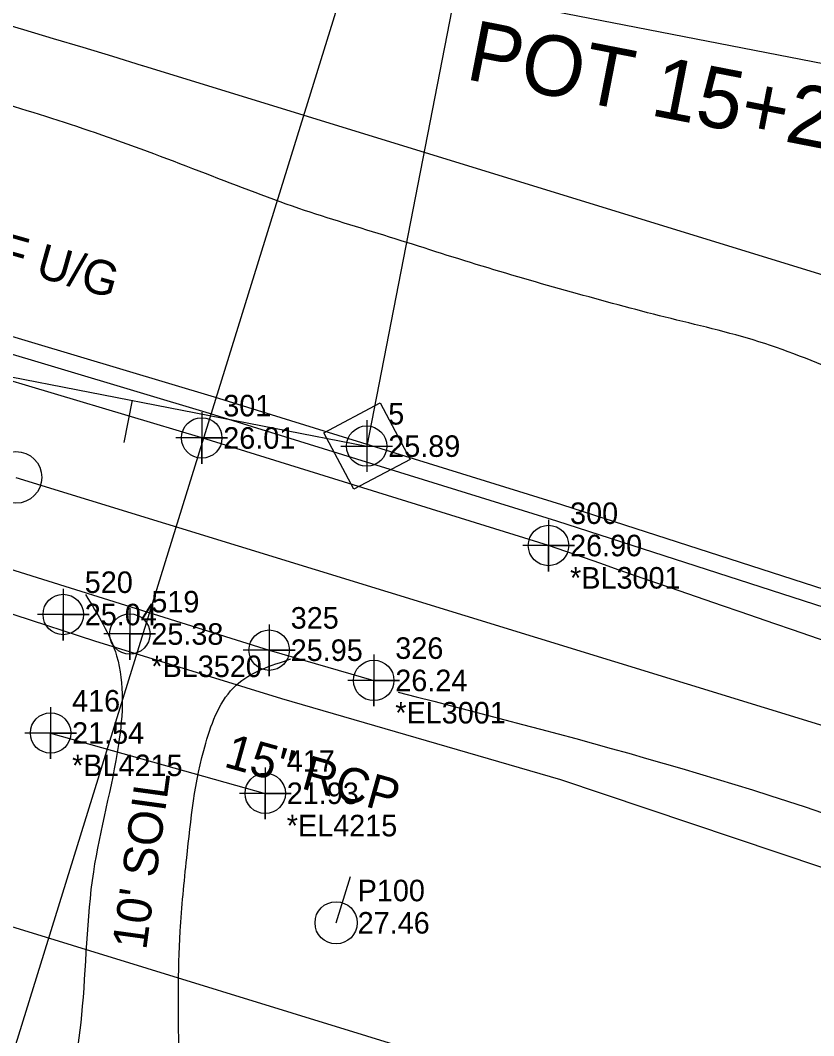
# Model space of a CAD drawing. Extents: x 2627243 to 2636458, y 566398 to 571062.
# Drawn here: x 2635089.6 to 2635181.7, y 568953.4 to 569071.3 of the extents above; entities that cross this region are included whole.
import ezdxf

# ---------------------------------------------------------------- set-up
doc = ezdxf.new("R2010")
doc.units = 0
for name, color, linetype in [('COGO Default Chain', 7, 'Continuous'), ('Cogo Default Point CELL', 7, 'Continuous'), ('COGO Default Point Elevation', 7, 'Continuous'), ('COGO Default Point Number', 7, 'Continuous'), ('CTL Supplemental Horizontal and Vertical CELL', 7, 'Continuous'), ('Default', 7, 'Continuous'), ('Exist Horizontal Alignment', 7, 'Continuous'), ('Exist Horizontal Alignment Point', 7, 'Continuous'), ('Exist Horizontal Baseline Alignment', 7, 'Continuous'), ('Exist Horizontal Baseline Alignment Station Label', 7, 'Continuous'), ('Exist Horizontal Baseline Alignment Tick small', 7, 'Continuous'), ('Exist Right of Way Line', 7, 'Continuous'), ('Exist Roads EOP', 7, 'Continuous'), ('Exist Roads EOP Cogo Comment', 7, 'Continuous'), ('Exist Roads EOP Cogo Elevation', 7, 'Continuous'), ('Exist Roads EOP Cogo Number', 7, 'Continuous'), ('Exist Roads EOP Cogo Point CELL', 7, 'Continuous'), ('Exist Roads Soil', 7, 'Continuous'), ('Exist Roads Soil Text', 7, 'Continuous'), ('Exist Structure Minor Pipes RCP 15 Inch', 7, 'Continuous'), ('Exist Structure Minor Pipes RCP 15 Inch Cogo Comment', 7, 'Continuous'), ('Exist Structure Minor Pipes RCP 15 Inch Cogo Elevation', 7, 'Continuous'), ('Exist Structure Minor Pipes RCP 15 Inch Cogo Number', 7, 'Continuous'), ('Exist Structure Minor Pipes RCP 15 Inch Cogo Point CELL', 7, 'Continuous'), ('Exist Structure Minor Pipes RCP 15 Inch Text', 7, 'Continuous'), ('Exist Utilities Power Pole CELL', 7, 'Continuous'), ('Exist Utilities Power Pole Cogo Elevation', 7, 'Continuous'), ('Exist Utilities Power Pole Cogo Number', 7, 'Continuous'), ('Exist Utilities Telephone UG Cable', 7, 'Continuous'), ('Exist Utilities Telephone UG Cable Text', 7, 'Continuous'), ('Exist Utilities Water UG Line Cogo Comment', 7, 'Continuous'), ('Exist Utilities Water UG Line Cogo Elevation', 7, 'Continuous'), ('Exist Utilities Water UG Line Cogo Number', 7, 'Continuous'), ('Exist Utilities Water UG Line Cogo Point CELL', 7, 'Continuous'), ('Exist Utilities Water UG Line SUE', 7, 'Continuous'), ('Exist Vegetation Woods Line', 7, 'Continuous'), ('Scratch_Level_2', 7, 'Continuous')]:
    doc.layers.add(name, color=color, linetype=linetype)

# ---------------------------------------------------------------- blocks, each defined once
blk = doc.blocks.new('COGO DEFAULT POINT')
at = {"layer": 'Cogo Default Point CELL'}
for points in [[(0, 0.06), (0, 0)], [(-0.06, 0), (0, 0)], [(0, 0), (0.06, 0)], [(0, 0), (0, -0.06)]]:
    blk.add_lwpolyline(points, dxfattribs=at)
blk.add_circle((0, 0), 0.0469, dxfattribs=at)
blk = doc.blocks.new('EXIST ROADS EOP COGO POINT')
at = {"layer": 'Exist Roads EOP Cogo Point CELL'}
blk.add_lwpolyline([(0, 0.06), (0, -0.06), (0, 0), (0.06, 0), (-0.06, 0)], dxfattribs=at)
blk.add_circle((0, 0), 0.0469, dxfattribs=at)
blk = doc.blocks.new('EXIST STRUCTURE MINOR PIPES RCP COGO POINT')
at = {"layer": 'Exist Structure Minor Pipes RCP 15 Inch Cogo Point CELL'}
blk.add_lwpolyline([(0, 0.06), (0, -0.06), (0, 0), (0.06, 0), (-0.06, 0)], dxfattribs=at)
blk.add_circle((0, 0), 0.0469, dxfattribs=at)
blk = doc.blocks.new('EXIST UTILITIES WATER UG LINE COGO POINT')
at = {"layer": 'Exist Utilities Water UG Line Cogo Point CELL'}
blk.add_lwpolyline([(0, 0.06), (0, -0.06), (0, 0), (0.06, 0), (-0.06, 0)], dxfattribs=at)
blk.add_circle((0, 0), 0.0469, dxfattribs=at)
blk = doc.blocks.new('EXIST UTILITIES POWER POLE')
at = {"layer": 'Exist Utilities Power Pole CELL'}
for q in [(0, 0.1125), (0, 0)]:
    blk.add_line((0, 0), q, dxfattribs=at)
blk.add_circle((0, 0), 0.049, dxfattribs=at)
blk = doc.blocks.new('CTL SUPPLEMENTAL HORIZONTAL AND VERTICAL')
at = {"layer": 'CTL Supplemental Horizontal and Vertical CELL'}
blk.add_line((0, 0), (0, 0), dxfattribs=at)
blk.add_lwpolyline([(-0.1043, 0.0004), (0.0005, 0.1052), (0.1055, 0.0002), (0.0007, -0.1047)], close=True, dxfattribs=at)

msp = doc.modelspace()

# ---------------------------------------------------------------- linework, layer by layer
at = {"layer": 'COGO Default Chain'}
msp.add_line((2635089.07, 569018.2), (2635391.77, 568925.15), dxfattribs=at)
msp.add_line((2635089.07, 569018.2), (2635391.77, 568925.15), dxfattribs=at)
at = {"layer": 'Exist Horizontal Alignment'}
msp.add_line((2635089.07, 569018.2), (2635391.77, 568925.15), dxfattribs=at)
at = {"layer": 'Exist Horizontal Alignment Point'}
msp.add_circle((2635089.07, 569018.2), 3, dxfattribs=at)
at = {"layer": 'Exist Horizontal Baseline Alignment'}
msp.add_line((2634680.61, 569109.43), (2635129.79, 569021.83), dxfattribs=at)
at = {"layer": 'Exist Horizontal Baseline Alignment Station Label'}
for q in [(2635129.79, 569021.83), (2635187.68, 569065.28)]:
    msp.add_line((2635140.07, 569074.57), q, dxfattribs=at)
at = {"layer": 'Exist Horizontal Baseline Alignment Tick small'}
msp.add_line((2635102.55, 569027.15), (2635101.59, 569022.24), dxfattribs=at)
at = {"layer": 'Exist Right of Way Line'}
for p, q in [((2635103.76, 569066), (2635803.01, 568851.04)), ((2635074.38, 568970.41), (2635740.72, 568765.57))]:
    msp.add_line(p, q, dxfattribs=at)
msp.add_arc((2634692.38, 567727.8), 1400, 72.91185, 82.32218, dxfattribs=at)
at = {"layer": 'Exist Roads EOP'}
for points in [[(2635150.9, 569010.29), (2635110.64, 569022.78), (2635067.86, 569035.57), (2635023.64, 569048.11), (2634984.83, 569056.94), (2634943.78, 569065.62), (2634903.89, 569072.16), (2634856.98, 569078.75), (2634806.21, 569085.47), (2634756.15, 569092.13), (2634708.47, 569098.26)], [(2634739.19, 569072.43), (2634781.28, 569066.95), (2634828.08, 569061.02), (2634863.8, 569056.89), (2634909.63, 569049.84), (2634954.36, 569041.99), (2634993.78, 569033.88), (2635035.22, 569023.11), (2635076.05, 569011.42), (2635118.47, 568998.14), (2635130.61, 568994.63)]]:
    msp.add_lwpolyline(points, dxfattribs=at)
for points in [[(2635667.16, 568849.05), (2635611.87, 568866.17), (2635537.66, 568888.99), (2635465.1, 568910.99), (2635418.27, 568925.45), (2635347.57, 568947.27), (2635276.81, 568969.36), (2635215.72, 568988.32), (2635150.9, 569010.29)], [(2635133.46, 568993.27), (2635198.85, 568973.26), (2635239.36, 568960.01), (2635248.88, 568959.46), (2635293.13, 568945.35), (2635367.48, 568922.3), (2635452.26, 568896.08), (2635526.55, 568873.61), (2635591.22, 568853.69), (2635664.39, 568831.49)]]:
    msp.add_spline(points, degree=3, dxfattribs=at)
at = {"layer": 'Exist Roads Soil'}
for points in [[(2635097.14, 569004.59), (2635100.76, 568997.47), (2635100.98, 568987.21), (2635098.06, 568972.41), (2635096.68, 568955.79), (2635094.68, 568941.66), (2635094.11, 568930.19), (2635096.85, 568919.53), (2635099.85, 568908.12), (2635102.17, 568895.97), (2635108.88, 568878.63), (2635115.77, 568864.28)], [(2635133.55, 568866.82), (2635129.28, 568877.14), (2635121.85, 568893), (2635113.93, 568911.65), (2635108.58, 568929.12), (2635107.96, 568937.38), (2635107.97, 568951.4), (2635108.13, 568965.51), (2635108.9, 568974.02), (2635111.1, 568987.34), (2635114.62, 568994.07), (2635121, 568997.12)]]:
    msp.add_spline(points, degree=3, dxfattribs=at)
at = {"layer": 'Exist Structure Minor Pipes RCP 15 Inch'}
msp.add_line((2635093.09, 568988.52), (2635118.01, 568981.52), dxfattribs=at)
at = {"layer": 'Exist Utilities Telephone UG Cable'}
for points in [[(2634914.07, 569075.55), (2634944.7, 569070.54), (2634985.9, 569061.82), (2635024.88, 569052.96), (2635069.26, 569040.37), (2635112.09, 569027.56), (2635152.41, 569015.06), (2635241.49, 568986.31)], [(2634912.04, 569073.86), (2634944.33, 569068.57), (2634985.47, 569059.87), (2635024.38, 569051.02), (2635068.7, 569038.45), (2635111.51, 569025.65), (2635151.81, 569013.15), (2635242.78, 568983.79)]]:
    msp.add_lwpolyline(points, dxfattribs=at)
at = {"layer": 'Exist Utilities Water UG Line SUE'}
msp.add_lwpolyline([(2634745.29, 569060.81), (2634772.3, 569060.34), (2634799.29, 569058.16), (2634834.92, 569055.15), (2634876.42, 569050.41), (2634893.17, 569047.22), (2634922.73, 569041.34), (2634951.3, 569036.03), (2634995.75, 569027.26), (2635043.17, 569015.78), (2635070.42, 569008.3), (2635098.21, 568999.23), (2635119.9, 568992.52), (2635152.3, 568983.11), (2635187.64, 568971.23), (2635214.87, 568960.8)], dxfattribs=at)
at = {"layer": 'Exist Vegetation Woods Line'}
msp.add_spline([(2635649.22, 568878.38), (2635649.32, 568878.23), (2635637.74, 568881.93), (2635627.68, 568886.16), (2635617.49, 568889.28), (2635607.89, 568892.77), (2635596.11, 568897.78), (2635585.94, 568901.53), (2635574.03, 568905.43), (2635563.97, 568908.01), (2635552.13, 568911.13), (2635540.53, 568914.2), (2635528.58, 568918.49), (2635517.15, 568923.92), (2635505.87, 568929.45), (2635493.79, 568934.28), (2635482.45, 568937.92), (2635472.8, 568941.17), (2635463.24, 568944.27), (2635450.66, 568948.58), (2635439.69, 568951.62), (2635428.91, 568954.37), (2635419.18, 568956.75), (2635408.99, 568959.87), (2635397.38, 568963.96), (2635387.75, 568967.84), (2635376.76, 568971.9), (2635365.81, 568975.58), (2635356.14, 568978.2), (2635343.89, 568980.65), (2635330.64, 568983.72), (2635319.31, 568987.36), (2635308.9, 568991.16), (2635296.37, 568995.71), (2635286.29, 568999.31), (2635275.75, 569003.66), (2635265.84, 569006.33), (2635254.74, 569009.92), (2635243.26, 569013.46), (2635232.29, 569016.51), (2635221.8, 569019.45), (2635210.06, 569022.42), (2635198.81, 569025.91), (2635186.75, 569029.72), (2635176, 569033.73), (2635165.13, 569036.63), (2635154.25, 569039.52), (2635143.19, 569042.72), (2635132.43, 569046.1), (2635121.91, 569049.42), (2635110.35, 569053.75), (2635098.3, 569058.19), (2635086.72, 569061.88), (2635075.7, 569064.69), (2635065.45, 569065.92), (2635055.37, 569067.87), (2635043.05, 569071.1), (2635032.79, 569073.35), (2635022.28, 569075.66), (2635011.74, 569078.35), (2635001.01, 569081.34), (2634990.29, 569084.33), (2634977.78, 569087.86), (2634972.57, 569088.94), (2634968.39, 569090.04), (2634959.01, 569094.49), (2634948.1, 569099.43), (2634938.51, 569104.57), (2634928.51, 569110.69), (2634919.34, 569115.47), (2634907.33, 569119.52), (2634897.4, 569121.57), (2634887.58, 569122.45)], degree=3, dxfattribs=at)
at = {"layer": 'Scratch_Level_2'}
for p, q in [((2635137.19, 569107.8), (2635107.6, 569012.28)), ((2635107.6, 569012.28), (2635078, 568916.76))]:
    msp.add_line(p, q, dxfattribs=at)

# ---------------------------------------------------------------- block references
at = {"layer": 'Cogo Default Point CELL', "xscale": 50, "yscale": 50}
msp.add_blockref('COGO DEFAULT POINT', (2635129.79, 569021.83), dxfattribs=at)
at = {"layer": 'CTL Supplemental Horizontal and Vertical CELL', "xscale": 50, "yscale": 49.99999999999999, "rotation": -17.088147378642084}
msp.add_blockref('CTL SUPPLEMENTAL HORIZONTAL AND VERTICAL', (2635129.79, 569021.83), dxfattribs=at)
at = {"layer": 'Exist Roads EOP Cogo Point CELL', "xscale": 50, "yscale": 50}
for p in [(2635110.64, 569022.78), (2635150.9, 569010.29), (2635118.47, 568998.14), (2635130.61, 568994.63)]:
    msp.add_blockref('EXIST ROADS EOP COGO POINT', p, dxfattribs=at)
at = {"layer": 'Exist Structure Minor Pipes RCP 15 Inch Cogo Point CELL', "xscale": 50, "yscale": 50}
for p in [(2635093.09, 568988.52), (2635118.01, 568981.52)]:
    msp.add_blockref('EXIST STRUCTURE MINOR PIPES RCP COGO POINT', p, dxfattribs=at)
at = {"layer": 'Exist Utilities Power Pole CELL', "xscale": 50, "yscale": 50.00000000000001, "rotation": -17.08814737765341}
msp.add_blockref('EXIST UTILITIES POWER POLE', (2635126.24, 568966.49), dxfattribs=at)
at = {"layer": 'Exist Utilities Water UG Line Cogo Point CELL', "xscale": 50, "yscale": 50}
for p in [(2635094.56, 569002.28), (2635102.29, 569000.02)]:
    msp.add_blockref('EXIST UTILITIES WATER UG LINE COGO POINT', p, dxfattribs=at)

# ---------------------------------------------------------------- texts
at = {"layer": 'COGO Default Point Elevation'}
msp.add_text('25.89', height=2.5, dxfattribs=at).set_placement((2635132.29, 569020.58))
at = {"layer": 'COGO Default Point Number'}
msp.add_text('5', height=2.5, dxfattribs=at).set_placement((2635132.29, 569024.33))
at = {"layer": 'Default'}
msp.add_text('POT 15+27.75 ', height=7, rotation=348.9655, dxfattribs=at).set_placement((2635141.13, 569064.46))
at = {"layer": 'Exist Roads EOP Cogo Comment'}
for s, p in [('*BL3001', (2635153.4, 569005.29)), ('*EL3001', (2635133.11, 568989.63))]:
    msp.add_text(s, height=2.5, dxfattribs=at).set_placement(p)
at = {"layer": 'Exist Roads EOP Cogo Elevation'}
for s, p in [('26.01', (2635113.14, 569021.53)), ('26.90', (2635153.4, 569009.04)), ('25.95', (2635120.97, 568996.89)), ('26.24', (2635133.11, 568993.38))]:
    msp.add_text(s, height=2.5, dxfattribs=at).set_placement(p)
at = {"layer": 'Exist Roads EOP Cogo Number'}
for s, p in [('301', (2635113.14, 569025.28)), ('300', (2635153.4, 569012.79)), ('325', (2635120.97, 569000.64)), ('326', (2635133.11, 568997.13))]:
    msp.add_text(s, height=2.5, dxfattribs=at).set_placement(p)
at = {"layer": 'Exist Roads Soil Text'}
msp.add_text("10' SOIL", height=4, rotation=82.2066, dxfattribs=at).set_placement((2635104.19, 568963.25))
at = {"layer": 'Exist Structure Minor Pipes RCP 15 Inch Cogo Comment'}
for s, p in [('*BL4215', (2635095.59, 568983.52)), ('*EL4215', (2635120.51, 568976.53))]:
    msp.add_text(s, height=2.5, dxfattribs=at).set_placement(p)
at = {"layer": 'Exist Structure Minor Pipes RCP 15 Inch Cogo Elevation'}
for s, p in [('21.54', (2635095.59, 568987.27)), ('21.93', (2635120.51, 568980.28))]:
    msp.add_text(s, height=2.5, dxfattribs=at).set_placement(p)
at = {"layer": 'Exist Structure Minor Pipes RCP 15 Inch Cogo Number'}
for s, p in [('416', (2635095.59, 568991.02)), ('417', (2635120.51, 568984.03))]:
    msp.add_text(s, height=2.5, dxfattribs=at).set_placement(p)
at = {"layer": 'Exist Structure Minor Pipes RCP 15 Inch Text'}
msp.add_text('15" RCP', height=4, rotation=344.3222, dxfattribs=at).set_placement((2635113.08, 568984.65))
at = {"layer": 'Exist Utilities Power Pole Cogo Elevation'}
msp.add_text('27.46', height=2.5, dxfattribs=at).set_placement((2635128.74, 568965.24))
at = {"layer": 'Exist Utilities Power Pole Cogo Number'}
msp.add_text('P100', height=2.5, dxfattribs=at).set_placement((2635128.74, 568968.99))
at = {"layer": 'Exist Utilities Telephone UG Cable Text'}
msp.add_text('APPROXIMATE LOCATION OF U/G', height=4, rotation=344.164, dxfattribs=at).set_placement((2635016.28, 569062.8))
at = {"layer": 'Exist Utilities Water UG Line Cogo Comment'}
msp.add_text('*BL3520', height=2.5, dxfattribs=at).set_placement((2635104.79, 568995.02))
at = {"layer": 'Exist Utilities Water UG Line Cogo Elevation'}
for s, p in [('25.04', (2635097.06, 569001.03)), ('25.38', (2635104.79, 568998.77))]:
    msp.add_text(s, height=2.5, dxfattribs=at).set_placement(p)
at = {"layer": 'Exist Utilities Water UG Line Cogo Number'}
for s, p in [('520', (2635097.06, 569004.78)), ('519', (2635104.79, 569002.52))]:
    msp.add_text(s, height=2.5, dxfattribs=at).set_placement(p)

doc.saveas('drawing.dxf')
